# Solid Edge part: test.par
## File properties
Title: Thrust bearing
Author: Abhinav Rai
Template: Normal.par
Last saved by: Cadcim
Revision: 9
Application: Solid Edge
Material: aluminum
Accuracy: 0.99
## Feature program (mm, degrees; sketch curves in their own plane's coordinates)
sketch for "unnamed RevolvedProtrusion 1" plane through (0, 0, 0) normal (0, -1, 0) x-axis (1, 0, 0)
  line (47.625, 16.8036) -> (66.929, 16.8036)
  line (66.929, 16.8036) -> (73.025, 10.7076)
  line (73.025, 10.7076) -> (73.025, -12.0254)
  line (73.025, -12.0254) -> (66.929, -18.1214)
  line (66.929, -18.1214) -> (47.625, -18.1214)
  line (47.625, -18.1214) -> (47.625, -7.1994)
  line (61.5714, -7.1994) -> (47.625, -7.1994)
  line (61.5714, 5.8816) -> (61.5714, -7.1994)
  line (47.625, 5.8816) -> (61.5714, 5.8816)
  line (47.625, 5.8816) -> (47.625, 16.8036)
revolve "unnamed RevolvedProtrusion 1" add finite 360 deg
sketch for "unnamed RevolvedProtrusion 2" plane through (0, 0, 0) normal (1, 0, 0) x-axis (0, 1, 0)
  line (69.977, 13.7556) -> (73.0652, 13.7556)
  line (73.0652, 13.7556) -> (74.6125, 12.2083)
  line (74.6125, 12.2083) -> (74.6125, -13.4669)
  line (74.6125, -13.4669) -> (73.006, -15.0734)
  line (73.006, -15.0734) -> (69.977, -15.0734)
revolve "unnamed RevolvedProtrusion 2" add full turn 360 deg
sketch for "unnamed RevolvedProtrusion 3" plane through (0, 0, 0) normal (0, -1, 0) x-axis (1, 0, 0)
revolve "unnamed RevolvedProtrusion 3" add full turn 360 deg about sketch line (-54.9674, 10.1232) -> (-54.9674, -18.1214)
pattern "unnamed Pattern 1" of "unnamed RevolvedProtrusion 3"
pattern "unnamed Pattern 2"
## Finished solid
Body 1: solid body, 39 faces, 39 edges, 25 vertices.
  Faces by surface: torus 25, plane 6, cone 4, cylinder 4
  Edges by curve: circle 39
Bounding box of the edges (mm; curved faces can reach further): 149.225 x 149.225 x 34.925, from (-74.6125, -74.6125, -18.1214) to (74.6125, 74.6125, 16.8036).
Cylindrical faces by radius (mm): R47.625 x2, R61.5714 x1, R74.6125 x1
Conical faces (half-angle, radius in mm at the cone's reference point): 45 deg R66.929 x1, 45 deg R73.025 x1, 45 deg R73.0652 x1, 45 deg R74.6125 x1
Toroidal faces (ring radius, tube radius in mm): R-0.1023 r6.604 x25
Planar faces by outward normal: +z 3, -z 3
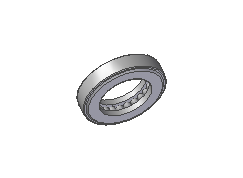
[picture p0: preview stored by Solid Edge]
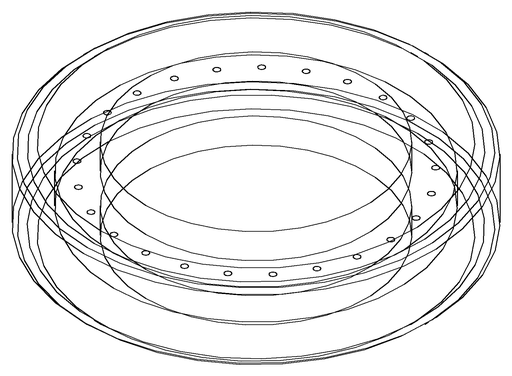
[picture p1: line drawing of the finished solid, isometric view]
